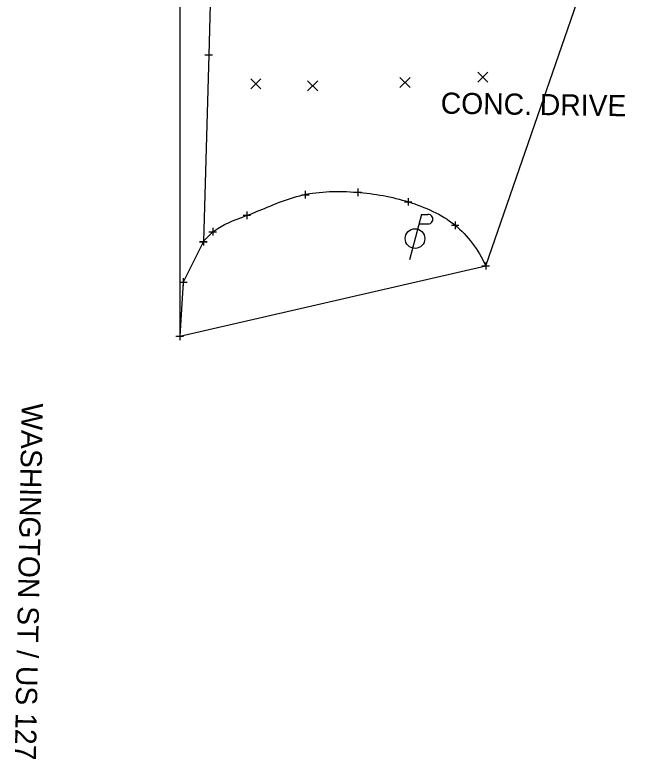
# Model space of a CAD drawing. Extents: x 1392719 to 1392850, y 437833 to 438309.
# Drawn here: x 1392751.8 to 1392836.5, y 437832.7 to 437931.1 of the extents above; entities that cross this region are included whole.
import ezdxf

# ---------------------------------------------------------------- set-up
doc = ezdxf.new("R2010")
doc.units = 0
for name, color, linetype in [('PV_P_Curb_Ramp', 7, 'Continuous'), ('PV_X_EOP', 7, 'Continuous'), ('RD_P_Fence', 7, 'Continuous'), ('SC_Scratch6', 7, 'Continuous'), ('SV_X_Terrain_Boundary', 7, 'Continuous'), ('TX_X_20', 7, 'Continuous')]:
    doc.layers.add(name, color=color, linetype=linetype)

msp = doc.modelspace()

# ---------------------------------------------------------------- linework, layer by layer
at = {"layer": 'PV_P_Curb_Ramp'}
for p, q in [((1392805.57, 437904.761), (1392803.963, 437898.761)), ((1392805.57, 437904.761), (1392806.42, 437904.761)), ((1392805.228, 437903.486), (1392806.42, 437903.486))]:
    msp.add_line(p, q, dxfattribs=at)
msp.add_circle((1392804.713, 437901.561), 1.3, dxfattribs=at)
msp.add_arc((1392806.432, 437904.123), 0.638, 268.8767, 91.1233, dxfattribs=at)
at = {"layer": 'PV_X_EOP'}
msp.add_lwpolyline([(1392775.84, 438041.527), (1392775.139, 438041.438), (1392774.596, 438023.273), (1392774.455, 438016.732), (1392774.273, 438006.861), (1392773.79, 437982.569), (1392773.613, 437973.697), (1392774.676, 437973.647), (1392774.4, 437957.607), (1392775.011, 437951.431), (1392777.984, 437945.863), (1392777.432, 437925.849), (1392776.728, 437901.157), (1392774.065, 437895.811), (1392773.599, 437888.633)], dxfattribs=at)
msp.add_open_spline([(1392776.724, 437901.123), (1392777.1, 437901.615), (1392778.614, 437903.326), (1392783.576, 437904.896), (1392789.64, 437907.795), (1392797.139, 437907.904), (1392803.888, 437906.687), (1392810.387, 437903.803), (1392813.039, 437900.126), (1392814.061, 437897.949)], degree=3, dxfattribs=at)
at = {"layer": 'RD_P_Fence'}
for p, q in [((1392782.981, 437921.362), (1392784.315, 437922.698)), ((1392782.981, 437922.698), (1392784.315, 437921.362)), ((1392802.719, 437921.532), (1392804.053, 437922.867)), ((1392802.719, 437922.867), (1392804.053, 437921.532)), ((1392813.024, 437922.242), (1392814.358, 437923.576)), ((1392813.024, 437923.576), (1392814.358, 437922.242)), ((1392790.511, 437921.104), (1392791.845, 437922.439)), ((1392790.511, 437922.439), (1392791.845, 437921.104))]:
    msp.add_line(p, q, dxfattribs=at)
at = {"layer": 'SC_Scratch6'}
for p, q in [((1392776.932, 437925.849), (1392777.932, 437925.849)), ((1392777.432, 437926.349), (1392777.432, 437925.349)), ((1392777.432, 437925.849), (1392777.432, 437925.849)), ((1392797.139, 437908.181), (1392797.139, 437907.181)), ((1392789.699, 437907.359), (1392790.699, 437907.359)), ((1392790.199, 437907.859), (1392790.199, 437906.859)), ((1392790.199, 437907.359), (1392790.199, 437907.359)), ((1392796.639, 437907.681), (1392797.639, 437907.681)), ((1392797.139, 437907.681), (1392797.139, 437907.681)), ((1392803.304, 437906.422), (1392804.304, 437906.422)), ((1392803.804, 437906.922), (1392803.804, 437905.922)), ((1392803.804, 437906.422), (1392803.804, 437906.422)), ((1392782.463, 437905.136), (1392782.463, 437904.136)), ((1392781.963, 437904.636), (1392782.963, 437904.636)), ((1392782.463, 437904.636), (1392782.463, 437904.636)), ((1392809.526, 437903.316), (1392810.526, 437903.316)), ((1392810.026, 437903.816), (1392810.026, 437902.816)), ((1392810.026, 437903.316), (1392810.026, 437903.316)), ((1392777.459, 437902.456), (1392778.459, 437902.456)), ((1392777.959, 437902.956), (1392777.959, 437901.956)), ((1392777.959, 437902.456), (1392777.959, 437902.456)), ((1392776.224, 437901.123), (1392777.224, 437901.123)), ((1392776.228, 437901.157), (1392777.228, 437901.157)), ((1392776.724, 437901.623), (1392776.724, 437900.623)), ((1392776.724, 437901.123), (1392776.724, 437901.123)), ((1392776.728, 437901.657), (1392776.728, 437900.657)), ((1392776.728, 437901.157), (1392776.728, 437901.157)), ((1392814.061, 437898.449), (1392814.061, 437897.449)), ((1392813.561, 437897.949), (1392814.561, 437897.949)), ((1392814.061, 437897.949), (1392814.061, 437897.949)), ((1392774.065, 437896.311), (1392774.065, 437895.311)), ((1392773.565, 437895.811), (1392774.565, 437895.811)), ((1392774.065, 437895.811), (1392774.065, 437895.811)), ((1392773.099, 437888.633), (1392774.099, 437888.633)), ((1392773.599, 437889.133), (1392773.599, 437888.133)), ((1392773.599, 437888.633), (1392773.599, 437888.633))]:
    msp.add_line(p, q, dxfattribs=at)
at = {"layer": 'SV_X_Terrain_Boundary'}
msp.add_lwpolyline([(1392773.599, 437888.633), (1392814.061, 437897.949), (1392835.824, 437960.81), (1392836.464, 437972.743), (1392818.576, 438061.039), (1392787.876, 438062.949), (1392775.139, 438041.438), (1392774.596, 438023.273), (1392774.455, 438016.732), (1392773.613, 437973.697)], close=True, dxfattribs=at)

# ---------------------------------------------------------------- texts
at = {"layer": 'TX_X_20'}
for s, rotation, p in [('CONC. DRIVE', 359.16965, (1392808.097, 437918.083)), ('WASHINGTON ST / US 127', 268.86093, (1392752.712, 437879.784))]:
    msp.add_text(s, height=2.79999, rotation=rotation, dxfattribs=at).set_placement(p)

doc.saveas('drawing.dxf')
